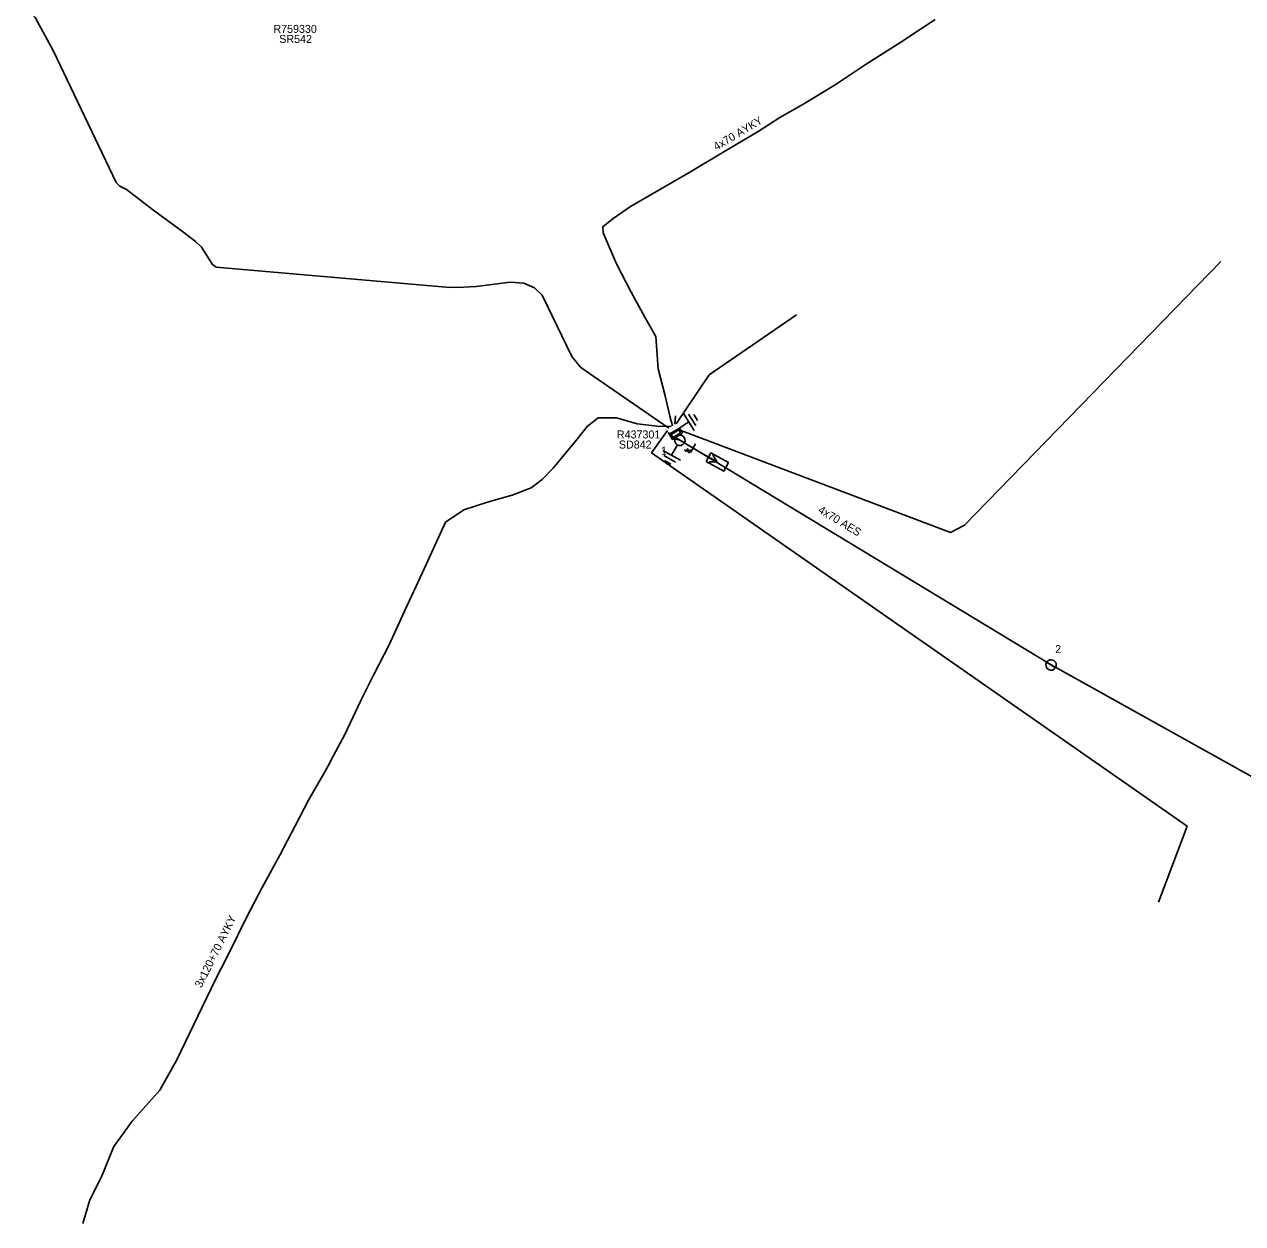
# Model space of a CAD drawing. Extents: x -540028 to -538776, y -1157064 to -1155670.
# Drawn here: x -539593.3 to -539441, y -1157028.9 to -1156879 of the extents above; entities that cross this region are included whole.
import ezdxf

# ---------------------------------------------------------------- set-up
doc = ezdxf.new("R2010")
doc.units = 0
for name, color, linetype in [('Implicitní', 7, 'Continuous'), ('Vrstva 13', 7, 'Continuous'), ('Vrstva 14', 7, 'Continuous'), ('Vrstva 15', 7, 'Continuous'), ('Vrstva 16', 7, 'Continuous'), ('Vrstva 18', 7, 'Continuous'), ('Vrstva 2', 7, 'Continuous'), ('Vrstva 28', 7, 'Continuous'), ('Vrstva 29', 7, 'Continuous'), ('Vrstva 30', 7, 'Continuous'), ('Vrstva 5', 7, 'Continuous'), ('Vrstva 50', 7, 'Continuous'), ('Vrstva 51', 7, 'Continuous'), ('Vrstva 52', 7, 'Continuous'), ('Vrstva 59', 7, 'Continuous'), ('Vrstva 6', 7, 'Continuous')]:
    doc.layers.add(name, color=color, linetype=linetype)

# ---------------------------------------------------------------- blocks, each defined once
blk = doc.blocks.new('5')
at = {"layer": 'Implicitní'}
blk.add_line((1.3, 0), (-1.3, 0), dxfattribs=at)
blk.add_arc((0, 0), 1.3, 180, 0, dxfattribs=at)
at = {"layer": 'Vrstva 2'}
blk.add_arc((0, 0), 1.3, 0, 180, dxfattribs=at)
blk = doc.blocks.new('NN840')
at = {"layer": 'Vrstva 15'}
for points in [[(0, 0.62), (0, -0.63)], [(-0.75, -0.71), (-0.75, -0.66)], [(-0.73, -0.76), (-0.75, -0.71)], [(-0.66, -0.8), (-0.73, -0.76)], [(-0.63, -0.8), (-0.66, -0.8)], [(-0.56, -0.76), (-0.63, -0.8)], [(-0.54, -0.71), (-0.56, -0.76)], [(-0.54, -0.38), (-0.54, -0.71)], [(-0.33, -0.38), (-0.33, -0.8)], [(-0.33, -0.64), (-0.13, -0.38)], [(-0.26, -0.56), (-0.09, -0.8)]]:
    blk.add_lwpolyline(points, dxfattribs=at)
blk = doc.blocks.new('12')
at = {"layer": 'Vrstva 2'}
for p, q in [((0, 0), (5, 0)), ((5, 0), (3.232, 0.936)), ((5, 0), (3.232, -0.936))]:
    blk.add_line(p, q, dxfattribs=at)
blk.add_lwpolyline([(2.5, -1.2), (7.5, -1.2), (7.5, 1.2), (2.5, 1.2)], close=True, dxfattribs=at)
blk = doc.blocks.new('132')
at = {"layer": 'Vrstva 2'}
for points in [[(-1.5, 1.5), (1.5, 1.5), (1.5, 0), (-1.5, 0)], [(-1.1, 1.2), (1.1, 1.2), (1.1, 0.3), (-1.1, 0.3)]]:
    blk.add_lwpolyline(points, close=True, dxfattribs=at)
blk = doc.blocks.new('11')
at = {"layer": 'Vrstva 2'}
for p, q in [((0, -4.3), (0, -1.3)), ((-2.5, -4.3), (2.5, -4.3)), ((-1.7, -5.3), (1.7, -5.3)), ((-0.9, -6.3), (0.9, -6.3))]:
    blk.add_line(p, q, dxfattribs=at)

msp = doc.modelspace()

# ---------------------------------------------------------------- linework, layer by layer
at = {"layer": 'Vrstva 5'}
for points in [[(-539593.27, -1156876.4), (-539592.29, -1156877.71), (-539591.91, -1156878.14), (-539589.65, -1156882.26), (-539581.78, -1156898.74), (-539581.33, -1156899.22), (-539580.52, -1156899.63), (-539577.27, -1156902.13), (-539573.34, -1156904.99), (-539571.9, -1156906.11), (-539571.14, -1156906.85), (-539569.76, -1156909.02), (-539569.31, -1156909.35), (-539540.12, -1156911.88), (-539538.41, -1156911.85), (-539536.83, -1156911.74), (-539532.56, -1156911.23), (-539530.86, -1156911.33), (-539529.53, -1156911.92), (-539528.55, -1156912.83), (-539524.85, -1156920.51), (-539523.76, -1156921.84), (-539522.77, -1156922.53), (-539512.75, -1156929.47)], [(-539512.29, -1156929.15), (-539512.63, -1156927.95), (-539513.19, -1156925.42), (-539514.06, -1156922.03), (-539514.37, -1156918), (-539515.73, -1156915.6), (-539517.44, -1156912.48), (-539519.26, -1156908.92), (-539520.93, -1156905.04), (-539521, -1156904.29), (-539519.7, -1156903.26), (-539517.54, -1156901.76), (-539514.08, -1156899.76), (-539510.31, -1156897.59), (-539505.43, -1156894.68), (-539501.58, -1156892.39), (-539498.86, -1156890.65), (-539496.09, -1156889.06), (-539491.96, -1156886.56), (-539488.1, -1156883.96), (-539483.76, -1156881.21), (-539479.44, -1156878.38)], [(-539585.98, -1157028.86), (-539585.1, -1157025.88), (-539583.64, -1157023.03), (-539582.08, -1157019.23), (-539579.79, -1157016.04), (-539576.33, -1157012.19), (-539574.23, -1157008.38), (-539572.13, -1157004.07), (-539569.37, -1156998.36), (-539567.83, -1156995.37), (-539565.42, -1156990.44), (-539563.55, -1156986.85), (-539561.34, -1156982.8), (-539559.44, -1156979.15), (-539557.75, -1156975.96), (-539555.74, -1156972.42), (-539555.31, -1156971.64), (-539554.67, -1156970.46), (-539553.23, -1156967.73), (-539551.28, -1156963.58), (-539549.58, -1156960.24), (-539547.7, -1156956.51), (-539545.76, -1156952.33), (-539543.51, -1156947.51), (-539540.63, -1156941.21), (-539538.34, -1156939.67), (-539535.29, -1156938.68), (-539532.32, -1156937.81), (-539529.94, -1156936.93), (-539528.57, -1156935.87), (-539527.2, -1156934.44), (-539524.2, -1156930.83), (-539522.95, -1156929.23), (-539521.55, -1156928.18), (-539519.26, -1156928.17), (-539516.68, -1156928.93), (-539514.19, -1156929.22), (-539512.45, -1156929.26)], [(-539511.35, -1156930.97), (-539512.24, -1156930.76), (-539512.83, -1156929.98)]]:
    msp.add_lwpolyline(points, dxfattribs=at)
at = {"layer": 'Vrstva 50'}
msp.add_lwpolyline([(-539511.35, -1156930.97), (-539508.87, -1156932.47), (-539464.97, -1156959.05), (-539431.85, -1156977.47), (-539403.42, -1156993.56)], dxfattribs=at)
at = {"layer": 'Vrstva 52'}
for points in [[(-539511.81, -1156928.92), (-539507.7, -1156922.8), (-539496.8, -1156915.3)], [(-539512.92, -1156929.73), (-539514.9, -1156932.54), (-539447.95, -1156979.21)], [(-539511.64, -1156929.58), (-539477.56, -1156942.49), (-539475.79, -1156941.56)]]:
    msp.add_lwpolyline(points, dxfattribs=at)
at = {"layer": 'Vrstva 59'}
for points in [[(-539475.79, -1156941.56), (-539443.75, -1156908.62)], [(-539511.97, -1156928.97), (-539511.92, -1156927.91)], [(-539447.95, -1156979.21), (-539451.56, -1156988.67)]]:
    msp.add_lwpolyline(points, dxfattribs=at)

# ---------------------------------------------------------------- block references
at = {"layer": 'Vrstva 13'}
for p, xscale, yscale, rotation in [((-539511.35, -1156930.97), 0.5000000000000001, 0.5, -31.137155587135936), ((-539464.97, -1156959.05), 0.49999999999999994, 0.5000000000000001, -31.191716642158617)]:
    msp.add_blockref('5', p, dxfattribs=dict(at, xscale=xscale, yscale=yscale, rotation=rotation))
at = {"layer": 'Vrstva 15', "xscale": 0.5, "yscale": 0.5}
for p, rotation in [((-539512.05, -1156929.83), 122.47374303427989), ((-539511.35, -1156930.97), -28.999999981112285)]:
    msp.add_blockref('11', p, dxfattribs=dict(at, rotation=rotation))
at = {"layer": 'Vrstva 16', "xscale": 0.5, "yscale": 0.5, "rotation": -28.999999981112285}
msp.add_blockref('12', (-539508.87, -1156932.47), dxfattribs=at)
at = {"layer": 'Vrstva 18', "rotation": -31.192111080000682}
msp.add_blockref('NN840', (-539509.72, -1156931.96), dxfattribs=at)
at = {"layer": 'Vrstva 28', "xscale": 0.5, "yscale": 0.5, "rotation": -148.44861512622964}
msp.add_blockref('132', (-539512.05, -1156929.83), dxfattribs=at)

# ---------------------------------------------------------------- texts
at = {"layer": 'Vrstva 14'}
for s, p in [('1', (-539513.73, -1156932.78)), ('2', (-539464.46, -1156957.57))]:
    msp.add_text(s, height=1, dxfattribs=at).set_placement(p)
at = {"layer": 'Vrstva 29'}
for s, p in [('R759330', (-539562.15, -1156880.06)), ('R437301', (-539519.23, -1156930.74))]:
    msp.add_text(s, height=1, dxfattribs=at).set_placement(p)
at = {"layer": 'Vrstva 30'}
for s, p in [('SR542', (-539561.42, -1156881.32)), ('SD842', (-539518.98, -1156932))]:
    msp.add_text(s, height=1, dxfattribs=at).set_placement(p)
at = {"layer": 'Vrstva 51'}
msp.add_text('4x70 AES', height=1, rotation=328.808, dxfattribs=at).set_placement((-539494.19, -1156939.94))
at = {"layer": 'Vrstva 6'}
for s, rotation, p in [('4x70 AYKY', 30.808, (-539506.79, -1156894.79)), ('3x120+70 AYKY', 63.444, (-539571.15, -1156999.47))]:
    msp.add_text(s, height=1, rotation=rotation, dxfattribs=at).set_placement(p)

doc.saveas('drawing.dxf')
